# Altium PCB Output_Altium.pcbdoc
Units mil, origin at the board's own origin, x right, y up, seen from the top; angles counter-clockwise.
Board outline 39000 x 39000 mil, 2 copper layers (Top Layer, Bottom Layer); 0 components, 0 nets, 42 pads, 0 vias.
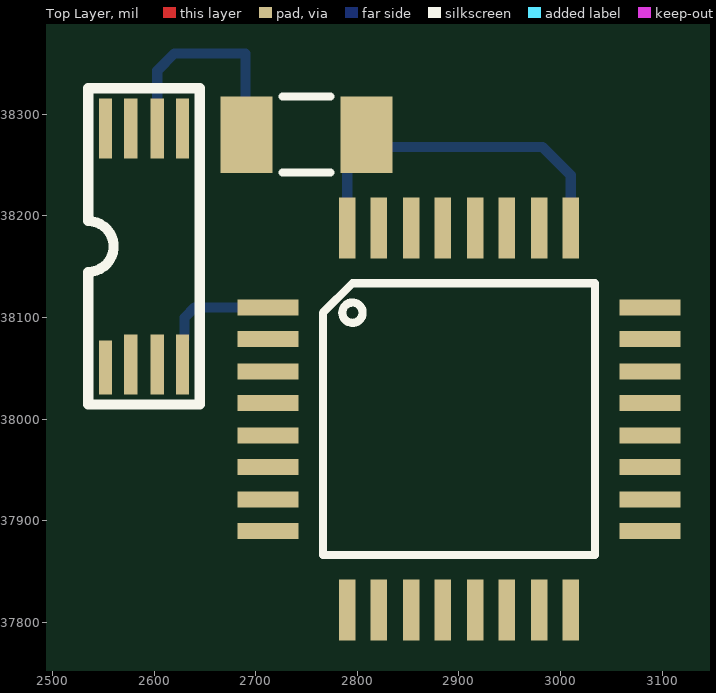
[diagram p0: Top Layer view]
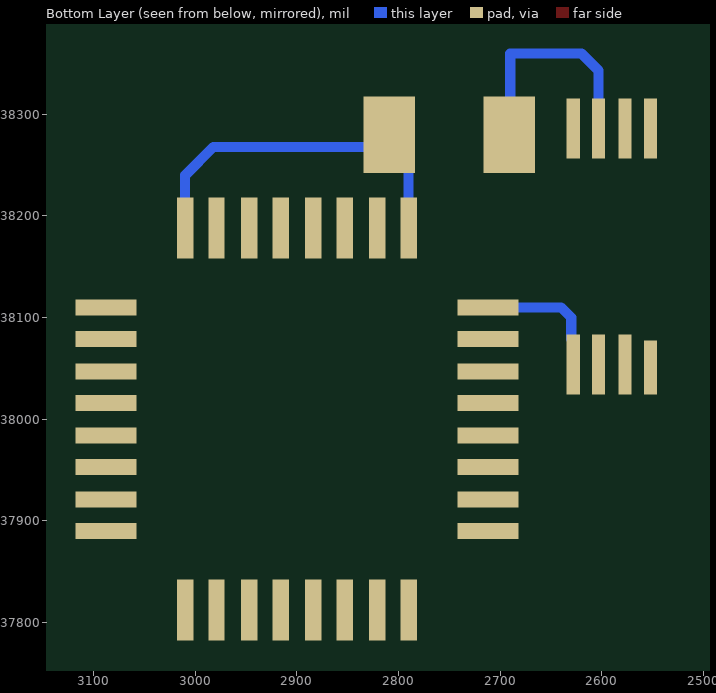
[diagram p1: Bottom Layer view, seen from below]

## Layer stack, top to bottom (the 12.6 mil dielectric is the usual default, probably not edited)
Top Layer: signal copper 1.4
Dielectric: dielectric 12.6, FR-4, Dk 4.8
Bottom Layer: signal copper 1.4

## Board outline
1000,1000 40000,1000 40000,40000 1000,40000

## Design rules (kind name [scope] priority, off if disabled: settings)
Clearance [All] p0: scope1count=1 scope1_0_kind=Board scope1_0_value=Board scope2count=1 scope2_0_kind=Board scope2_0_value=Board commentlength=0 gap=10
Clearance [All] p1: gap=10
ComponentClearance [All] p0: scope1count=1 scope1_0_kind=Board scope1_0_value=Board scope2count=1 scope2_0_kind=Board scope2_0_value=Board commentlength=0 gap=10 collisioncheckmode=3
ComponentClearance [All] p1: gap=10 collisioncheckmode=3 verticalgap=10
DiffPairsRouting [All] p0: scope1count=1 scope1_0_kind=Board scope1_0_value=Board scope2count=1 scope2_0_kind=Board scope2_0_value=Board commentlength=0
FanoutControl Fanout_BGA [All] p0 off: scope1count=1 scope1_0_kind=Board scope1_0_value=Board scope2count=1 scope2_0_kind=Board scope2_0_value=Board commentlength=69 // Protel DXP Scope 1 Expression Was: IsBGA   Fanout_BGA (Default Rule)
FanoutControl Fanout_LCC [All] p0 off: scope1count=1 scope1_0_kind=Board scope1_0_value=Board scope2count=1 scope2_0_kind=Board scope2_0_value=Board commentlength=69 // Protel DXP Scope 1 Expression Was: IsLCC   Fanout_LCC (Default Rule)
FanoutControl Fanout_SOIC [All] p0 off: scope1count=1 scope1_0_kind=Board scope1_0_value=Board scope2count=1 scope2_0_kind=Board scope2_0_value=Board commentlength=71 // Protel DXP Scope 1 Expression Was: IsSOIC   Fanout_SOIC (Default Rule)
FanoutControl Fanout_Small [All] p0 off: scope1count=1 scope1_0_kind=Board scope1_0_value=Board scope2count=1 scope2_0_kind=Board scope2_0_value=Board commentlength=84 // Protel DXP Scope 1 Expression Was: (CompPinCount < 5)   Fanout_Small (Default Rule)
FanoutControl Fanout_Default [All] p0: scope1count=1 scope1_0_kind=Board scope1_0_value=Board scope2count=1 scope2_0_kind=Board scope2_0_value=Board commentlength=30 // Fanout_Default (Default Rule)
Height [All] p0: scope1count=1 scope1_0_kind=Board scope1_0_value=Board scope2count=1 scope2_0_kind=Board scope2_0_value=Board commentlength=0
HoleSize [All] p0: scope1count=1 scope1_0_kind=Board scope1_0_value=Board scope2count=1 scope2_0_kind=Board scope2_0_value=Board commentlength=0 absolutevalues=TRUE maxlimit=100 minlimit=1 maxpercent=80.000 minpercent=20.000
LayerPairs [All] p0: scope1count=1 scope1_0_kind=Board scope1_0_value=Board scope2count=1 scope2_0_kind=Board scope2_0_value=Board commentlength=0 enforce=TRUE
PasteMaskExpansion [All] p0: scope1count=1 scope1_0_kind=Board scope1_0_value=Board scope2count=1 scope2_0_kind=Board scope2_0_value=Board commentlength=0 expansion=0
PlaneClearance [All] p0: scope1count=1 scope1_0_kind=Board scope1_0_value=Board scope2count=1 scope2_0_kind=Board scope2_0_value=Board commentlength=0 clearance=20
PlaneConnect [All] p0: scope1count=1 scope1_0_kind=Board scope1_0_value=Board scope2count=1 scope2_0_kind=Board scope2_0_value=Board commentlength=0 planeconnectstyle=Relief reliefexpansion=20 reliefentries=4 reliefconductorwidth=10 reliefairgap=10
PolygonConnect [All] p0: scope1count=1 scope1_0_kind=Board scope1_0_value=Board scope2count=1 scope2_0_kind=Board scope2_0_value=Board commentlength=0 connectstyle=Relief reliefconductorwidth=10 reliefentries=4 polygonreliefangle="90 Angle"
PolygonConnect [All] p1: connectstyle=Relief reliefconductorwidth=10 reliefentries=4 polygonreliefangle="90 Angle"
RoutingCorners [All] p0: scope1count=1 scope1_0_kind=Board scope1_0_value=Board scope2count=1 scope2_0_kind=Board scope2_0_value=Board commentlength=0 cornerstyle=45-Degree minsetback=100 maxsetback=100
RoutingLayers [All] p0: scope1count=1 scope1_0_kind=Board scope1_0_value=Board scope2count=1 scope2_0_kind=Board scope2_0_value=Board commentlength=0 top layer=Automatic bottom layer=Automatic
RoutingPriority [All] p0: scope1count=1 scope1_0_kind=Board scope1_0_value=Board scope2count=1 scope2_0_kind=Board scope2_0_value=Board commentlength=0
RoutingTopology [All] p0: scope1count=1 scope1_0_kind=Board scope1_0_value=Board scope2count=1 scope2_0_kind=Board scope2_0_value=Board commentlength=0 topology=Shortest
RoutingVias [All] p0: scope1count=1 scope1_0_kind=Board scope1_0_value=Board scope2count=1 scope2_0_kind=Board scope2_0_value=Board commentlength=0 holewidth=28 width=50 viastyle="Through Hole" minholewidth=28 minwidth=50 maxholewidth=28 maxwidth=50
RoutingVias [All] p1: holewidth=28 width=50 viastyle="Through Hole" minholewidth=28 minwidth=50 maxholewidth=28 maxwidth=50
ShortCircuit [All] p0: scope1count=1 scope1_0_kind=Board scope1_0_value=Board scope2count=1 scope2_0_kind=Board scope2_0_value=Board commentlength=0 allowed=FALSE
SolderMaskExpansion [All] p0: scope1count=1 scope1_0_kind=Board scope1_0_value=Board scope2count=1 scope2_0_kind=Board scope2_0_value=Board commentlength=0 expansion=4
SolderMaskExpansion [All] p1: expansion=4
TestPointUsage [All] p0: scope1count=1 scope1_0_kind=Board scope1_0_value=Board scope2count=1 scope2_0_kind=Board scope2_0_value=Board commentlength=0 valid=0 allowmultiple=FALSE
TestPointUsage [All] p1: valid=0 allowmultiple=FALSE
Testpoint [All] p0: scope1count=1 scope1_0_kind=Board scope1_0_value=Board scope2count=1 scope2_0_kind=Board scope2_0_value=Board commentlength=0 side=15 testpointundercomponent=TRUE minsize=40 maxsize=100 preferedsize=60 minholesize=0 maxholesize=40 preferedholesize=32 testpointgrid=1 style=1023 order=0123456789
Testpoint [All] p1: side=15 testpointundercomponent=TRUE minsize=40 maxsize=100 preferedsize=60 minholesize=0 maxholesize=40 preferedholesize=32 testpointgrid=1 style=1023 order=0123456789
UnRoutedNet [All] p0: scope1count=1 scope1_0_kind=Board scope1_0_value=Board scope2count=1 scope2_0_kind=Board scope2_0_value=Board commentlength=0
Width [All] p0: scope1count=1 scope1_0_kind=Board scope1_0_value=Board scope2count=1 scope2_0_kind=Board scope2_0_value=Board commentlength=0 maxlimit=10 minlimit=10 preferedwidth=10
Width [All] p1: maxlimit=10 minlimit=10 preferedwidth=10
18 further rules are at their usual default settings.

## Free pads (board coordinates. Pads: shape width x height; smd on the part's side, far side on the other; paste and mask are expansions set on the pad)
  rect 13x53 all layers, no hole: 2(2552,38051)
  rect 13x59 all layers, no hole: 2(2552,38286) 2(2577,38054) 2(2577,38286) 2(2603,38054) 2(2603,38286) 2(2628,38054) 2(2628,38286)
  rect 51x75 all layers, no hole: 2(2691,38280) 2(2809,38280)
  rect 60x16 all layers, no hole: 2(2712,37890) 2(2712,37921) 2(2712,37953) 2(2712,37984) 2(2712,38016) 2(2712,38047) 2(2712,38079) 2(2712,38110) 2(3088,37890) 2(3088,37921) 2(3088,37953) 2(3088,37984) 2(3088,38016) 2(3088,38047) 2(3088,38079) 2(3088,38110)
  rect 16x60 all layers, no hole: 2(2790,37812) 2(2790,38188) 2(2821,37812) 2(2821,38188) 2(2853,37812) 2(2853,38188) 2(2884,37812) 2(2884,38188) 2(2916,37812) 2(2916,38188) 2(2947,37812) 2(2947,38188) 2(2979,37812) 2(2979,38188) 2(3010,37812) 2(3010,38188)

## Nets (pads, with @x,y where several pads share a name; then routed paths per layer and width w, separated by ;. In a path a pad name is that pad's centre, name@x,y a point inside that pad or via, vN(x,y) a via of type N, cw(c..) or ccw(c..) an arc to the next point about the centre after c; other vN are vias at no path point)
copper on no net: | length 592.9
  Bottom Layer w10: 2603,38309 2603,38343 2620,38360 2690,38360 2690,38293 2691,38292 ; 2628,38077 2630,38079 2630,38100 2640,38110 2690,38110 ; 2790,38210 2790,38249 2809,38268 2982,38268 3010,38240 3010,38210

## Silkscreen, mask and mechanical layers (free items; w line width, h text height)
Top Overlay:
  circle w8: c2795.21,38104.79 r10
  lines w8: 2726.38,38242.6 2773.62,38242.6 ; 2726.38,38317.4 2773.62,38317.4 ; 2766.21,37866.21 2766.21,38104.79 2795.21,38133.79 3033.79,38133.79 3033.79,37866.21 2766.21,37866.21
  lines w10: 2535.12,38014.34 2535.12,38145 ccw(c2535.12,38170) 2535.12,38195 2535.12,38325.66 2644.88,38325.66 2644.88,38014.34 2535.12,38014.34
